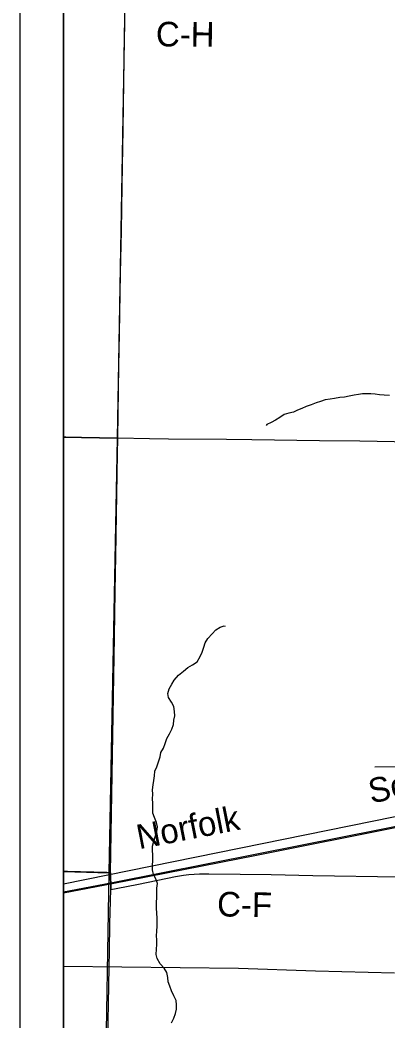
# Model space of a CAD drawing. Extents: x -21.7 to 34, y 0 to 22.
# Drawn here: x 23.417 to 24.265, y 16.163 to 18.47 of the extents above; entities that cross this region are included whole.
import ezdxf

# ---------------------------------------------------------------- set-up
doc = ezdxf.new("R2010")
doc.units = 0
for name, color, linetype in [('Default', 7, 'Continuous'), ('GM_X_County_Road', 7, 'Continuous'), ('GM_X_County_Road_Text', 7, 'Continuous'), ('GM_X_Interchange_Ramps', 7, 'Continuous'), ('GM_X_Minor_River', 7, 'Continuous'), ('GM_X_Rail_Line', 7, 'Continuous'), ('GM_X_Rail_Line_Text', 7, 'Continuous'), ('GM_X_State_Route', 7, 'Continuous'), ('GM_X_Township_Road', 7, 'Continuous'), ('GM_X_US_Route', 7, 'Continuous'), ('SH_Data', 7, 'Continuous')]:
    doc.layers.add(name, color=color, linetype=linetype)

msp = doc.modelspace()

# ---------------------------------------------------------------- linework, layer by layer
at = {"layer": 'Default'}
for points in [[(23.5167, 18.5124), (23.5167, 17.5078), (23.6412, 17.5054), (23.6589, 18.509)], [(23.5167, 17.5078), (23.5167, 16.5057), (23.6222, 16.5033), (23.6412, 17.5054)], [(23.5167, 16.5057), (23.5167, 15.5023), (23.6052, 15.5005), (23.6222, 16.5033)]]:
    msp.add_lwpolyline(points, close=True, dxfattribs=at)
at = {"layer": 'GM_X_County_Road'}
for points in [[(23.6418, 17.5061), (23.6446, 17.6719), (23.6457, 17.7465), (23.6483, 17.8864), (23.6502, 17.9827), (23.6521, 18.0884), (23.6541, 18.2189), (23.6576, 18.4334), (23.6587, 18.5088)], [(23.6255, 16.5033), (23.6343, 17.0472), (23.636, 17.1529), (23.6372, 17.2337), (23.6412, 17.4699), (23.6417, 17.5041), (23.6418, 17.5061)], [(23.5167, 16.5069), (23.5262, 16.5066), (23.6164, 16.5046), (23.6255, 16.5033)], [(23.6256, 16.4644), (23.6257, 16.466), (23.6255, 16.5033)], [(23.6256, 16.4644), (23.6379, 16.4668), (23.6898, 16.4767), (23.7751, 16.4941), (23.7934, 16.4974), (23.8057, 16.499), (23.818, 16.5001), (23.8304, 16.5007), (23.8521, 16.5009), (23.9236, 16.4998), (23.9951, 16.4988), (24.0915, 16.4969), (24.2904, 16.4939), (24.4085, 16.4918), (24.4798, 16.491), (24.4945, 16.4906), (24.5845, 16.4894), (24.6301, 16.4891)], [(23.6073, 15.5024), (23.6081, 15.5243), (23.6092, 15.5989), (23.6113, 15.7077), (23.6159, 15.9595), (23.617, 16.0154), (23.6181, 16.0651), (23.619, 16.1211), (23.6211, 16.2423), (23.6219, 16.2858), (23.6226, 16.3231), (23.6235, 16.3852), (23.6249, 16.4381), (23.6256, 16.4644)]]:
    msp.add_lwpolyline(points, dxfattribs=at)
at = {"layer": 'GM_X_Interchange_Ramps'}
msp.add_lwpolyline([(23.5167, 18.5138), (23.5167, 14.1), (27.5987, 14.1)], dxfattribs=at)
at = {"layer": 'GM_X_Minor_River'}
for points in [[(24.268, 17.6036), (24.2559, 17.6043), (24.2453, 17.6053), (24.2351, 17.6066), (24.2252, 17.608), (24.2157, 17.6078), (24.2059, 17.6076), (24.1963, 17.606), (24.1864, 17.6043), (24.175, 17.6026), (24.164, 17.6002), (24.1533, 17.599), (24.1415, 17.5969), (24.1312, 17.5956), (24.1198, 17.5936), (24.1091, 17.5897), (24.0992, 17.5873), (24.0877, 17.5826), (24.0758, 17.5783), (24.0662, 17.5736), (24.0563, 17.5704), (24.0467, 17.5656), (24.0364, 17.5628), (24.0257, 17.56), (24.0153, 17.5534), (24.0053, 17.5472), (23.9957, 17.5417), (23.9853, 17.5367), (23.9841, 17.5344)], [(23.7227, 16.6404), (23.7226, 16.6529), (23.7225, 16.6639), (23.7223, 16.6734), (23.723, 16.684), (23.7221, 16.6943), (23.7235, 16.706), (23.7249, 16.7159), (23.7266, 16.7268), (23.7272, 16.7371), (23.7317, 16.7472), (23.7361, 16.7593), (23.7394, 16.7702), (23.7412, 16.7808), (23.7471, 16.7905), (23.7511, 16.8011), (23.7552, 16.8131), (23.7615, 16.8232), (23.7663, 16.8345), (23.77, 16.845), (23.7713, 16.8549), (23.7735, 16.8654), (23.7726, 16.875), (23.7713, 16.8867), (23.7655, 16.8967), (23.7589, 16.9071), (23.7576, 16.9167), (23.7605, 16.9272), (23.7668, 16.9377), (23.7716, 16.9475), (23.7821, 16.9586), (23.7933, 16.9682), (23.8034, 16.9767), (23.8138, 16.9826), (23.8246, 16.9899), (23.8321, 17.0019), (23.8365, 17.0117), (23.8401, 17.0234), (23.8434, 17.0335), (23.8497, 17.0436), (23.8591, 17.0541), (23.8676, 17.0637), (23.8776, 17.0692), (23.8872, 17.0724), (23.8891, 17.072)], [(23.7661, 16.1571), (23.7713, 16.1676), (23.7746, 16.1785), (23.7774, 16.1883), (23.7769, 16.1986), (23.7764, 16.2081), (23.7713, 16.2192), (23.7659, 16.2307), (23.762, 16.2414), (23.7581, 16.2517), (23.7571, 16.2616), (23.7551, 16.2727), (23.7485, 16.2827), (23.7393, 16.2928), (23.7327, 16.3051), (23.7303, 16.3146), (23.731, 16.3271), (23.732, 16.3377), (23.7322, 16.3483), (23.7309, 16.3579), (23.7316, 16.3681), (23.733, 16.3798), (23.7328, 16.3893), (23.733, 16.3995), (23.7321, 16.4091), (23.7313, 16.422), (23.7312, 16.4345), (23.7319, 16.4463), (23.7323, 16.4675), (23.7334, 16.4781), (23.7298, 16.4888), (23.724, 16.4988), (23.7223, 16.5098), (23.7222, 16.5193), (23.7225, 16.5322), (23.7224, 16.5444), (23.7219, 16.5546), (23.7221, 16.5645), (23.725, 16.5758), (23.7279, 16.586), (23.732, 16.5981), (23.7334, 16.6087), (23.7309, 16.619), (23.7263, 16.6304), (23.7227, 16.6404)]]:
    msp.add_lwpolyline(points, dxfattribs=at)
at = {"layer": 'GM_X_Rail_Line'}
for points in [[(23.5167, 16.459), (23.6295, 16.4808), (23.9621, 16.5465), (24.6321, 16.6797), (25.2774, 16.8081), (25.8901, 16.9293), (26.3845, 17.0293), (27.0776, 17.1675), (27.7467, 17.2984), (28.3715, 17.4275), (28.9889, 17.5495), (29.6221, 17.6814), (30.2791, 17.8098), (30.3167, 17.8172)], [(23.5167, 16.4567), (23.6289, 16.4784), (23.9619, 16.5433), (24.6317, 16.6775), (25.2779, 16.8058), (25.8906, 16.927), (26.3849, 17.0271), (27.078, 17.1653), (27.7471, 17.2961), (28.3719, 17.4252), (28.9894, 17.5472), (29.6225, 17.6791), (30.2796, 17.8076), (30.3167, 17.8149)], [(23.5167, 16.4779), (24.4815, 16.6733), (25.8905, 16.9443)], [(24.4823, 16.708), (24.4395, 16.7376), (24.4157, 16.745), (24.3976, 16.7491), (24.3483, 16.7482), (24.234, 16.7466)], [(23.5167, 16.2873), (23.9204, 16.2834), (24.0979, 16.2768), (24.2799, 16.272)]]:
    msp.add_lwpolyline(points, dxfattribs=at)
at = {"layer": 'GM_X_State_Route'}
for points in [[(23.5167, 17.5085), (23.5222, 17.5084), (23.5844, 17.5072), (23.6418, 17.5061)], [(23.6418, 17.5061), (23.7149, 17.5048), (23.7585, 17.5042), (23.8922, 17.5029), (23.9512, 17.5023), (24.1067, 17.5004), (24.2, 17.499), (24.478, 17.4943)]]:
    msp.add_lwpolyline(points, dxfattribs=at)
at = {"layer": 'GM_X_Township_Road'}
for points in [[(23.5167, 16.5069), (23.5262, 16.5066), (23.6164, 16.5046), (23.6255, 16.5033)], [(23.6255, 16.5033), (23.6257, 16.466), (23.6256, 16.4644)], [(23.6256, 16.4644), (23.6379, 16.4668), (23.6898, 16.4767), (23.7751, 16.4941), (23.7934, 16.4974), (23.8057, 16.499), (23.818, 16.5001), (23.8304, 16.5007), (23.8521, 16.5009), (23.9236, 16.4998), (23.9951, 16.4988), (24.0915, 16.4969), (24.2904, 16.4939), (24.4085, 16.4918), (24.4798, 16.491), (24.4945, 16.4906), (24.5845, 16.4894), (24.6301, 16.4891)]]:
    msp.add_lwpolyline(points, dxfattribs=at)
at = {"layer": 'GM_X_US_Route'}
for points in [[(23.5167, 17.5085), (23.5222, 17.5084), (23.5844, 17.5072), (23.6418, 17.5061)], [(23.6418, 17.5061), (23.7149, 17.5048), (23.7585, 17.5042), (23.8922, 17.5029), (23.9512, 17.5023), (24.1067, 17.5004), (24.2, 17.499), (24.478, 17.4943)]]:
    msp.add_lwpolyline(points, dxfattribs=at)
at = {"layer": 'SH_Data'}
msp.add_line((23.5167, 20.9), (23.5167, 14.1), dxfattribs=at)
for points in [[(23.4167, 21), (30.4167, 21), (30.4167, 14), (23.4167, 14)], [(23.5167, 20.9), (30.3167, 20.9), (30.3167, 14.1), (23.5167, 14.1)]]:
    msp.add_lwpolyline(points, close=True, dxfattribs=at)

# ---------------------------------------------------------------- texts
at = {"layer": 'GM_X_County_Road_Text'}
for s, rotation, p in [('C-H', 359.6023, (23.7297, 18.4091)), ('C-F', 359.1191, (23.8705, 16.4025))]:
    msp.add_text(s, height=0.05682, rotation=rotation, dxfattribs=at).set_placement(p)
at = {"layer": 'GM_X_Rail_Line_Text'}
for s, rotation, p in [('Southern', 11.5058, (24.2257, 16.6628)), ('Norfolk', 11.0557, (23.6912, 16.5571))]:
    msp.add_text(s, height=0.05663, rotation=rotation, dxfattribs=at).set_placement(p)

doc.saveas('drawing.dxf')
